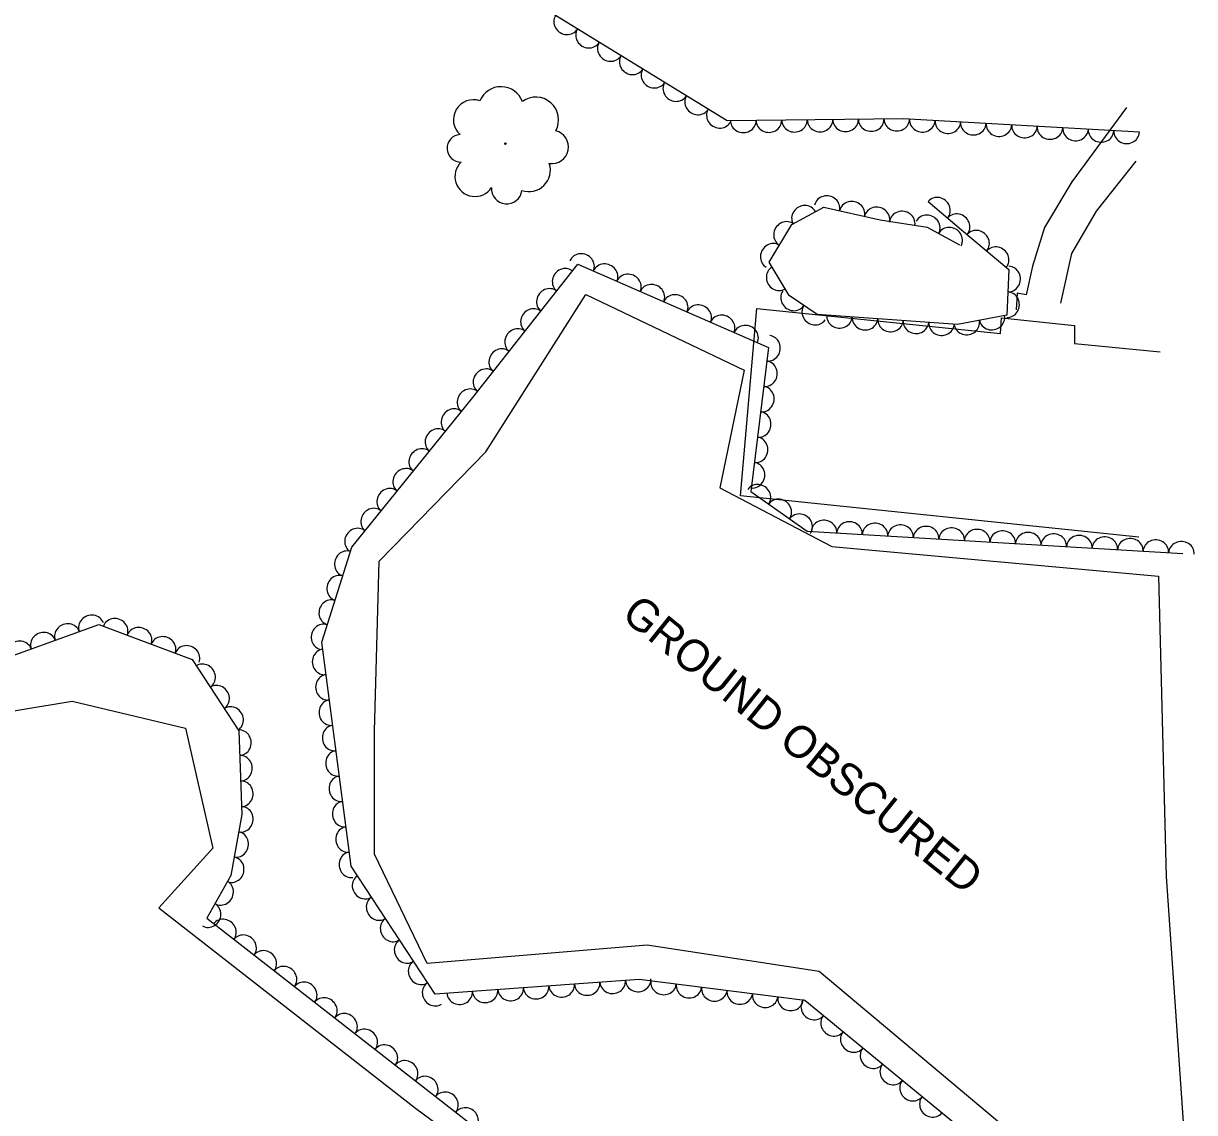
# Model space of a CAD drawing. Extents: x 1722896 to 1754269, y 648279 to 666297.
# Drawn here: x 1730625.5 to 1730808.6, y 652833.1 to 653003.5 of the extents above; entities that cross this region are included whole.
import ezdxf

# ---------------------------------------------------------------- set-up
doc = ezdxf.new("R2010")
doc.units = 0
for name, color, linetype in [('DESIGN - CENTERLINE - Proposed Text', 7, 'Continuous'), ('SURVEY - CENTERLINE - Preliminary', 7, 'Continuous'), ('SURVEY - VEGETATION - Features with Text', 7, 'Continuous')]:
    doc.layers.add(name, color=color, linetype=linetype)

msp = doc.modelspace()

# ---------------------------------------------------------------- linework, layer by layer
at = {"layer": 'DESIGN - CENTERLINE - Proposed Text'}
for points in [[(1730797.99, 652990.31), (1730789.43, 652978.68), (1730785.16, 652971.56), (1730783.3, 652965.52), (1730782.32, 652961.01), (1730780.89, 652961.29), (1730780.73, 652958.65)], [(1730787.73, 652959.74), (1730789.42, 652967.48), (1730793.27, 652974.09), (1730799.5, 652981.95)], [(1730799.89, 652923.1), (1730737.61, 652929.6), (1730740.17, 652958.91), (1730778.28, 652954.97), (1730778.45, 652957.41), (1730789.85, 652956.21), (1730789.83, 652953.39), (1730803.27, 652952.09)]]:
    msp.add_lwpolyline(points, dxfattribs=at)
at = {"layer": 'SURVEY - CENTERLINE - Preliminary'}
for points in [[(1730807.06, 652797.76), (1730780.73, 652829.3), (1730749.9, 652855.19), (1730723.01, 652859.3), (1730688.62, 652856.46), (1730680.37, 652873.54), (1730680.36, 652892.76), (1730681.12, 652919.34), (1730685.44, 652923.8), (1730697.79, 652936.46), (1730713.42, 652961.05), (1730738.2, 652949.22), (1730734.38, 652930.84), (1730751.89, 652921.68), (1730802.97, 652917), (1730804.21, 652870.04), (1730807.32, 652824.85), (1730807.06, 652797.76)], [(1730720.27, 652614.71), (1730706.25, 652625.32), (1730665.93, 652663.44), (1730626.63, 652722.75), (1730603.83, 652769.34), (1730599.26, 652771.7), (1730596.79, 652774.46), (1730593.52, 652786.22), (1730593.19, 652800.47), (1730599.08, 652827.8), (1730610.64, 652852.31), (1730617.3, 652894.86), (1730633.08, 652897.49), (1730650.84, 652893.26), (1730655.08, 652874.49), (1730646.65, 652865.12), (1730686.8, 652833.8), (1730736.98, 652796.74), (1730787.91, 652758.78), (1730758.05, 652705.53), (1730728.4, 652651.58), (1730720.27, 652614.71)]]:
    msp.add_lwpolyline(points, dxfattribs=at)
at = {"layer": 'SURVEY - VEGETATION - Features with Text'}
for points in [[(1730800, 652986.44), (1730763.05, 652988.54), (1730735.55, 652988.24), (1730705.02, 653006.93), (1730704.33, 653033.08), (1730712.44, 653047.63), (1730724.18, 653054.88), (1730742.17, 653059.66), (1730762.87, 653058), (1730785.66, 653065.43), (1730802.08, 653066.47)], [(1730766.95, 652975.62), (1730772.2, 652971.19), (1730779.58, 652964.96), (1730779.28, 652957.86), (1730771.54, 652956.38), (1730749.63, 652957.93), (1730745.23, 652960.9), (1730742.08, 652966.14), (1730745.65, 652972.04), (1730750.63, 652974.74), (1730759.46, 652972.74), (1730766.83, 652971.61), (1730771.85, 652968.84)], [(1730806.76, 652797.22), (1730775.89, 652827.5), (1730747.7, 652850.65), (1730721.78, 652853.91), (1730689.85, 652851.64), (1730676.75, 652871.66), (1730672.12, 652906.71), (1730676.85, 652921.56), (1730695.74, 652944.96), (1730712.19, 652965.82), (1730741.98, 652952.8), (1730739.22, 652930.27), (1730748.05, 652924.04), (1730806.81, 652920.55)], [(1730713.54, 652616.39), (1730684.15, 652641.11), (1730661.89, 652663.27), (1730622.32, 652724.18), (1730601.02, 652767.77), (1730595.5, 652771.51), (1730589.82, 652780.37), (1730590.1, 652793.94), (1730592.91, 652825.76), (1730599.98, 652857.72), (1730608.67, 652886.97), (1730619.32, 652903), (1730637.28, 652909.47), (1730651.84, 652903.97), (1730659.15, 652892.81), (1730659.64, 652879.72), (1730657.92, 652870.22), (1730654.14, 652863.51), (1730705.73, 652823.35), (1730767.98, 652778.32), (1730795.73, 652755.25)]]:
    msp.add_lwpolyline(points, dxfattribs=at)
msp.add_circle((1730700.86, 652984.67), 0.109, dxfattribs=at)
for centre, radius, start, end in [((1730700.16, 652990.01), 3.57, 20.1125, 157.6367), ((1730695.85, 652988.41), 3.13, 71.0597, 227.8487), ((1730705.63, 652988.41), 3.54, 331.0083, 126.8468), ((1730693.87, 652983.94), 2.15, 93.1759, 271.9215), ((1730708.11, 652984.15), 2.61, 261.2612, 76.2615), ((1730696.08, 652979.52), 3.12, 133.1966, 326.6163), ((1730704.51, 652980.53), 3.37, 251.1023, 17.948), ((1730701.06, 652977.63), 2.38, 175.8153, 353.1344)]:
    msp.add_arc(centre, radius, start, end, dxfattribs=at)
for centre, major_axis in [((1730710.4, 653003.64), (-1.71, 1.04)), ((1730713.81, 653001.55), (-1.71, 1.04)), ((1730717.22, 652999.46), (-1.71, 1.04)), ((1730720.64, 652997.38), (-1.71, 1.04)), ((1730724.05, 652995.29), (-1.71, 1.04)), ((1730727.46, 652993.2), (-1.71, 1.04)), ((1730730.87, 652991.11), (-1.71, 1.04)), ((1730734.28, 652989.02), (-1.71, 1.04)), ((1730738.06, 652988.27), (-2, -0.02)), ((1730742.06, 652988.31), (-2, -0.02)), ((1730746.06, 652988.36), (-2, -0.02)), ((1730750.06, 652988.4), (-2, -0.02)), ((1730754.06, 652988.44), (-2, -0.02)), ((1730758.06, 652988.48), (-2, -0.02)), ((1730762.06, 652988.53), (-2, -0.02)), ((1730766.06, 652988.37), (-2, 0.11)), ((1730770.05, 652988.14), (-2, 0.11)), ((1730774.04, 652987.91), (-2, 0.11)), ((1730778.04, 652987.69), (-2, 0.11)), ((1730782.03, 652987.46), (-2, 0.11)), ((1730786.02, 652987.23), (-2, 0.11)), ((1730790.02, 652987.01), (-2, 0.11)), ((1730794.01, 652986.78), (-2, 0.11)), ((1730798, 652986.56), (-2, 0.11)), ((1730751.16, 652974.62), (1.95, -0.44)), ((1730768.48, 652974.33), (1.53, -1.29)), ((1730747.59, 652973.09), (1.76, 0.95)), ((1730755.06, 652973.74), (1.95, -0.44)), ((1730758.96, 652972.85), (1.95, -0.44)), ((1730744.72, 652970.5), (1.04, 1.71)), ((1730762.91, 652972.21), (1.98, -0.3)), ((1730766.86, 652971.59), (1.75, -0.97)), ((1730771.54, 652971.75), (1.53, -1.29)), ((1730770.36, 652969.66), (1.75, -0.97)), ((1730774.59, 652969.17), (1.53, -1.29)), ((1730742.65, 652967.08), (1.04, 1.71)), ((1730712.78, 652965.56), (1.83, -0.8)), ((1730777.65, 652966.59), (1.53, -1.29)), ((1730710.11, 652963.18), (1.24, 1.57)), ((1730716.45, 652963.96), (1.83, -0.8)), ((1730743.57, 652963.66), (-1.03, 1.71)), ((1730779.52, 652963.49), (-0.08, -2)), ((1730720.11, 652962.36), (1.83, -0.8)), ((1730707.64, 652960.04), (1.24, 1.57)), ((1730723.78, 652960.75), (1.83, -0.8)), ((1730727.44, 652959.15), (1.83, -0.8)), ((1730745.88, 652960.46), (-1.66, 1.12)), ((1730779.35, 652959.49), (-0.08, -2)), ((1730705.16, 652956.9), (1.24, 1.57)), ((1730731.11, 652957.55), (1.83, -0.8)), ((1730734.77, 652955.95), (1.83, -0.8)), ((1730749.19, 652958.23), (-1.66, 1.12)), ((1730738.44, 652954.34), (1.83, -0.8)), ((1730753.1, 652957.69), (-1.99, 0.14)), ((1730757.09, 652957.4), (-1.99, 0.14)), ((1730761.08, 652957.12), (-1.99, 0.14)), ((1730765.07, 652956.84), (-1.99, 0.14)), ((1730769.06, 652956.55), (-1.99, 0.14)), ((1730773.02, 652956.66), (-1.96, -0.38)), ((1730776.95, 652957.42), (-1.96, -0.38)), ((1730702.68, 652953.76), (1.24, 1.57)), ((1730741.96, 652952.66), (-0.24, -1.99)), ((1730700.2, 652950.62), (1.24, 1.57)), ((1730741.48, 652948.69), (-0.24, -1.99)), ((1730697.73, 652947.48), (1.24, 1.57)), ((1730695.24, 652944.34), (1.26, 1.56)), ((1730740.99, 652944.72), (-0.24, -1.99)), ((1730692.73, 652941.23), (1.26, 1.56)), ((1730740.5, 652940.75), (-0.24, -1.99)), ((1730690.22, 652938.12), (1.26, 1.56)), ((1730740.01, 652936.78), (-0.24, -1.99)), ((1730687.7, 652935), (1.26, 1.56)), ((1730739.53, 652932.81), (-0.24, -1.99)), ((1730685.19, 652931.89), (1.26, 1.56)), ((1730682.68, 652928.78), (1.26, 1.56)), ((1730740.39, 652929.44), (1.63, -1.15)), ((1730743.66, 652927.14), (1.63, -1.15)), ((1730680.17, 652925.67), (1.26, 1.56)), ((1730746.93, 652924.83), (1.63, -1.15)), ((1730750.67, 652923.88), (2, -0.12)), ((1730754.67, 652923.65), (2, -0.12)), ((1730758.66, 652923.41), (2, -0.12)), ((1730762.65, 652923.17), (2, -0.12)), ((1730677.65, 652922.55), (1.26, 1.56)), ((1730766.65, 652922.93), (2, -0.12)), ((1730770.64, 652922.7), (2, -0.12)), ((1730774.63, 652922.46), (2, -0.12)), ((1730778.62, 652922.22), (2, -0.12)), ((1730782.62, 652921.98), (2, -0.12)), ((1730786.61, 652921.75), (2, -0.12)), ((1730790.6, 652921.51), (2, -0.12)), ((1730794.6, 652921.27), (2, -0.12)), ((1730798.59, 652921.03), (2, -0.12)), ((1730802.58, 652920.8), (2, -0.12)), ((1730806.58, 652920.56), (2, -0.12)), ((1730676.02, 652918.97), (0.61, 1.91)), ((1730674.81, 652915.15), (0.61, 1.91)), ((1730673.59, 652911.34), (0.61, 1.91)), ((1730636.09, 652909.04), (1.88, 0.68)), ((1730639.84, 652908.5), (1.87, -0.71)), ((1730628.57, 652906.33), (1.88, 0.68)), ((1730632.33, 652907.69), (1.88, 0.68)), ((1730643.58, 652907.09), (1.87, -0.71)), ((1730672.38, 652907.53), (0.61, 1.91)), ((1730624.8, 652904.98), (1.88, 0.68)), ((1730647.33, 652905.67), (1.87, -0.71)), ((1730651.07, 652904.26), (1.87, -0.71)), ((1730672.53, 652903.6), (-0.26, 1.98)), ((1730653.58, 652901.31), (1.1, -1.67)), ((1730673.05, 652899.64), (-0.26, 1.98)), ((1730655.77, 652897.97), (1.1, -1.67)), ((1730673.58, 652895.67), (-0.26, 1.98)), ((1730657.96, 652894.62), (1.1, -1.67)), ((1730659.21, 652890.97), (0.08, -2)), ((1730674.1, 652891.7), (-0.26, 1.98)), ((1730659.37, 652886.98), (0.08, -2)), ((1730674.62, 652887.74), (-0.26, 1.98)), ((1730659.52, 652882.98), (0.08, -2)), ((1730675.15, 652883.77), (-0.26, 1.98)), ((1730675.67, 652879.81), (-0.26, 1.98)), ((1730659.51, 652878.99), (-0.36, -1.97)), ((1730676.2, 652875.84), (-0.26, 1.98)), ((1730658.79, 652875.06), (-0.36, -1.97)), ((1730676.72, 652871.88), (-0.26, 1.98)), ((1730658.08, 652871.12), (-0.36, -1.97)), ((1730678.82, 652868.5), (-1.1, 1.67)), ((1730656.41, 652867.53), (-0.98, -1.74)), ((1730681.01, 652865.15), (-1.1, 1.67)), ((1730654.44, 652864.05), (-0.98, -1.74)), ((1730656.8, 652861.43), (1.58, -1.23)), ((1730683.2, 652861.8), (-1.1, 1.67)), ((1730659.96, 652858.97), (1.58, -1.23)), ((1730685.39, 652858.45), (-1.1, 1.67)), ((1730663.11, 652856.52), (1.58, -1.23)), ((1730666.27, 652854.06), (1.58, -1.23)), ((1730687.58, 652855.11), (-1.1, 1.67)), ((1730669.43, 652851.6), (1.58, -1.23)), ((1730717.63, 652853.61), (-1.99, -0.14)), ((1730721.62, 652853.9), (-1.99, -0.14)), ((1730725.59, 652853.43), (-1.98, 0.25)), ((1730689.77, 652851.76), (-1.1, 1.67)), ((1730693.69, 652851.91), (-1.99, -0.14)), ((1730697.68, 652852.19), (-1.99, -0.14)), ((1730701.67, 652852.48), (-1.99, -0.14)), ((1730705.66, 652852.76), (-1.99, -0.14)), ((1730709.65, 652853.05), (-1.99, -0.14)), ((1730713.64, 652853.33), (-1.99, -0.14)), ((1730729.56, 652852.93), (-1.98, 0.25)), ((1730733.53, 652852.43), (-1.98, 0.25)), ((1730737.5, 652851.93), (-1.98, 0.25)), ((1730672.58, 652849.15), (1.58, -1.23)), ((1730741.47, 652851.43), (-1.98, 0.25)), ((1730745.44, 652850.94), (-1.98, 0.25)), ((1730749.03, 652849.56), (-1.55, 1.27)), ((1730675.74, 652846.69), (1.58, -1.23)), ((1730752.12, 652847.02), (-1.55, 1.27)), ((1730678.9, 652844.23), (1.58, -1.23)), ((1730755.21, 652844.48), (-1.55, 1.27)), ((1730682.05, 652841.78), (1.58, -1.23)), ((1730758.3, 652841.94), (-1.55, 1.27)), ((1730685.21, 652839.32), (1.58, -1.23)), ((1730688.37, 652836.86), (1.58, -1.23)), ((1730761.39, 652839.41), (-1.55, 1.27)), ((1730764.48, 652836.87), (-1.55, 1.27)), ((1730691.52, 652834.4), (1.58, -1.23)), ((1730767.58, 652834.33), (-1.55, 1.27)), ((1730694.68, 652831.95), (1.58, -1.23))]:
    msp.add_ellipse(centre, major_axis=major_axis, ratio=0.940188, start_param=0, end_param=3.141593, dxfattribs=at)

# ---------------------------------------------------------------- texts
at = {"layer": 'SURVEY - CENTERLINE - Preliminary'}
msp.add_text('GROUND OBSCURED', height=5, rotation=321.1831, dxfattribs=at).set_placement((1730718.78, 652910.57))

doc.saveas('drawing.dxf')
